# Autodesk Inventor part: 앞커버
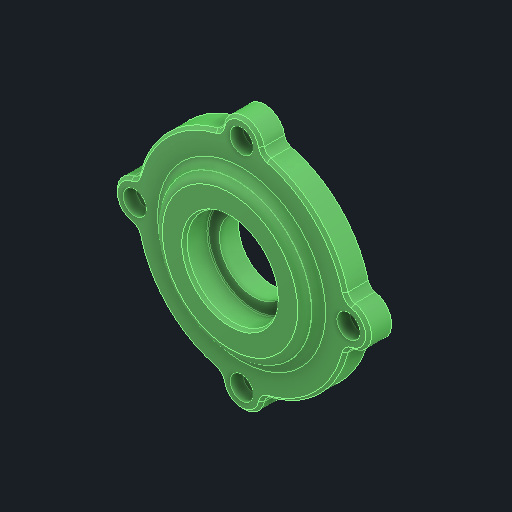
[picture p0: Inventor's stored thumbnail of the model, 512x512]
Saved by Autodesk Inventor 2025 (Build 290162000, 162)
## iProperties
Created: 2025-08
Part Number: 앞커버
Material: 알루미늄 6061
Document SubType Name: Modeling
Designer: infra012
Density: 2.71 g/cm^3
Appearance: 기본값
Company: 한국ATC센터
Author: jhkim
Sending System: Autodesk Inventor 2026
Preprocessor: ST-DEVELOPER v20.1
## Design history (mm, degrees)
sketch "스케치1"
  geometry: 1 further point
  constraints: 1 other
feature "솔리드1"
node "솔리드2"
